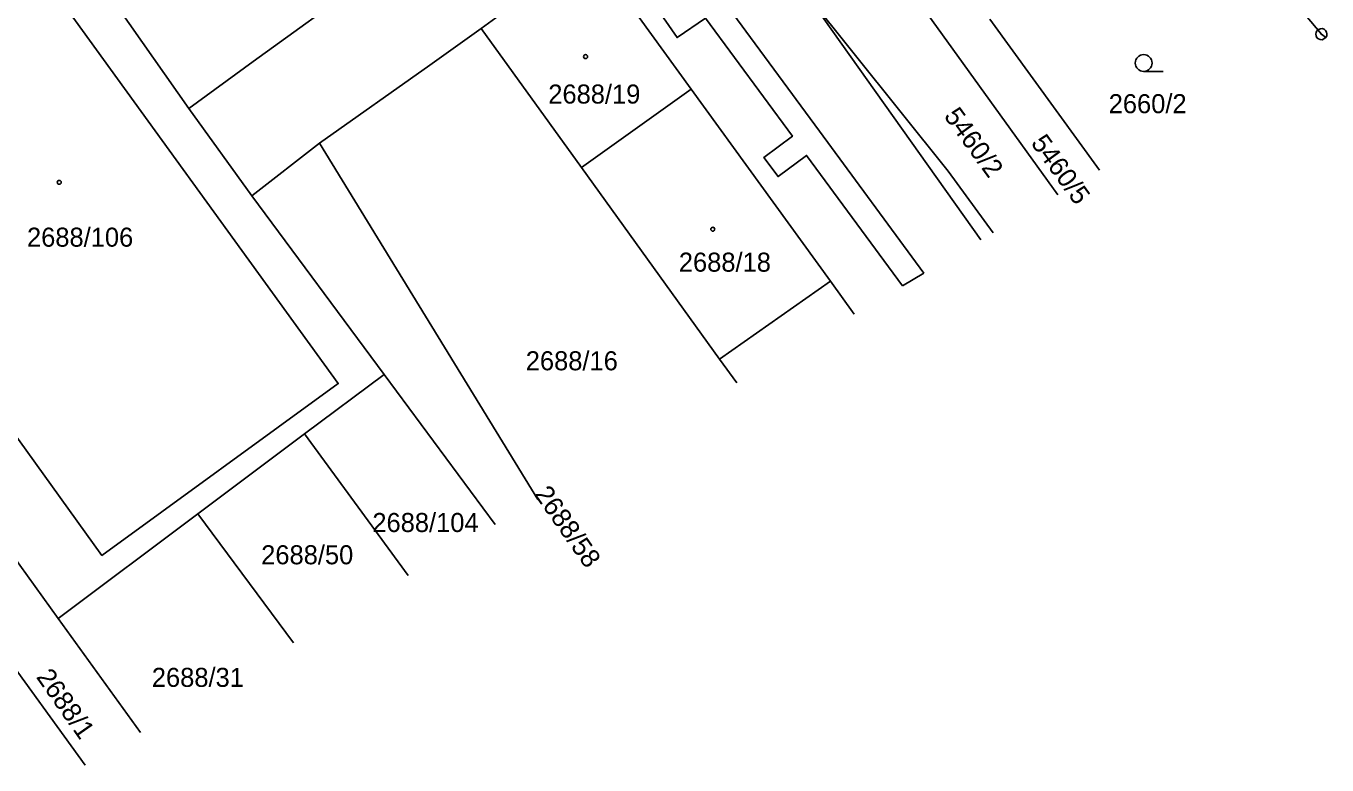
# Model space of a CAD drawing. Extents: x -821458 to -820266, y -1071458 to -1069826.
# Drawn here: x -820637.8 to -820521.7, y -1071458.4 to -1071392.4 of the extents above; entities that cross this region are included whole.
import ezdxf

# ---------------------------------------------------------------- set-up
doc = ezdxf.new("R2010")
doc.units = 0
for name, color, linetype in [('Vrstva 1', 7, 'Continuous'), ('Vrstva 13', 7, 'Continuous'), ('Vrstva 2', 7, 'Continuous'), ('Vrstva 3', 7, 'Continuous'), ('Vrstva 4', 7, 'Continuous'), ('Vrstva 5', 7, 'Continuous'), ('Vrstva 8', 7, 'Continuous')]:
    doc.layers.add(name, color=color, linetype=linetype)

msp = doc.modelspace()

# ---------------------------------------------------------------- linework, layer by layer
at = {"layer": 'Vrstva 1'}
for p, q in [((-820578.44, -1071398.07), (-820587.38, -1071385.73)), ((-820629.59, -1071390.8), (-820623.29, -1071399.8)), ((-820551.8, -1071391.81), (-820542, -1071405.29)), ((-820588.24, -1071405.05), (-820597.2, -1071392.64)), ((-820578.44, -1071398.07), (-820588.24, -1071405.05)), ((-820566.03, -1071415.2), (-820578.44, -1071398.07)), ((-820623.29, -1071399.8), (-820617.66, -1071407.57)), ((-820575.91, -1071422.15), (-820588.24, -1071405.05)), ((-820617.66, -1071407.57), (-820605.86, -1071423.52)), ((-820566.03, -1071415.2), (-820575.91, -1071422.15)), ((-820563.91, -1071418.13), (-820566.03, -1071415.2)), ((-820652.54, -1071420.92), (-820634.93, -1071445.29)), ((-820574.38, -1071424.27), (-820575.91, -1071422.15)), ((-820605.86, -1071423.52), (-820612.95, -1071428.83)), ((-820605.86, -1071423.52), (-820595.95, -1071436.92)), ((-820612.95, -1071428.83), (-820622.48, -1071435.96)), ((-820603.7, -1071441.46), (-820612.95, -1071428.83)), ((-820622.48, -1071435.96), (-820634.93, -1071445.29)), ((-820613.93, -1071447.46), (-820622.48, -1071435.96)), ((-820644.49, -1071441.9), (-820632.54, -1071458.37)), ((-820634.93, -1071445.29), (-820627.58, -1071455.46))]:
    msp.add_line(p, q, dxfattribs=at)
for points in [[(-820521.8, -1071393.45), (-820522.21, -1071393.16), (-820534.12, -1071378.97)], [(-820545.73, -1071407.48), (-820562.09, -1071384.76)], [(-820597.2, -1071392.64), (-820595.89, -1071391.71), (-820587.38, -1071385.73)], [(-820605.49, -1071386.9), (-820607.39, -1071388.24), (-820617.53, -1071395.61), (-820623.29, -1071399.8)], [(-820636.76, -1071387.29), (-820609.95, -1071424.33), (-820631.03, -1071439.67), (-820644.44, -1071421.08), (-820639.9, -1071417.79), (-820653.43, -1071399.1)], [(-820568.23, -1071389.49), (-820555.51, -1071405.39), (-820551.51, -1071410.87)], [(-820568.23, -1071389.49), (-820552.6, -1071411.51)], [(-820617.66, -1071407.57), (-820611.61, -1071402.88), (-820601.76, -1071395.91), (-820597.2, -1071392.64)]]:
    msp.add_lwpolyline(points, dxfattribs=at)
at = {"layer": 'Vrstva 13'}
msp.add_line((-820559.59, -1071415.6), (-820557.68, -1071414.49), dxfattribs=at)
for points in [[(-820557.68, -1071414.49), (-820567.01, -1071401.8), (-820575.97, -1071389.59)], [(-820580.91, -1071391.7), (-820579.71, -1071393.46), (-820577.16, -1071391.72), (-820569.42, -1071402.27), (-820571.96, -1071404.16), (-820570.7, -1071405.86), (-820568.15, -1071403.97), (-820559.59, -1071415.6)]]:
    msp.add_lwpolyline(points, dxfattribs=at)
at = {"layer": 'Vrstva 3'}
msp.add_line((-820538.07, -1071396.48), (-820536.32, -1071396.48), dxfattribs=at)
msp.add_circle((-820538.07, -1071395.73), 0.75, dxfattribs=at)
at = {"layer": 'Vrstva 4'}
msp.add_line((-820611.61, -1071402.88), (-820592.13, -1071434.68), dxfattribs=at)
at = {"layer": 'Vrstva 5'}
for centre in [(-820587.87, -1071395.16), (-820634.84, -1071406.38), (-820576.52, -1071410.56)]:
    msp.add_circle(centre, 0.175, dxfattribs=at)
at = {"layer": 'Vrstva 8'}
msp.add_line((-820522.15, -1071393.66), (-820521.81, -1071393.45), dxfattribs=at)
msp.add_circle((-820522.21, -1071393.16), 0.0303, dxfattribs=at)
msp.add_arc((-820522.21, -1071393.16), 0.5, 323.9672, 276.7903, dxfattribs=at)

# ---------------------------------------------------------------- texts
at = {"layer": 'Vrstva 2'}
for s, p in [('2688/19', (-820591.2, -1071399.35)), ('2660/2', (-820541.19, -1071400.21)), ('2688/106', (-820637.72, -1071412.12)), ('2688/18', (-820579.55, -1071414.35)), ('2688/16', (-820593.21, -1071423.15)), ('2688/104', (-820606.9, -1071437.58)), ('2688/50', (-820616.82, -1071440.46)), ('2688/31', (-820626.58, -1071451.4))]:
    msp.add_text(s, height=1.7, dxfattribs=at).set_placement(p)
for s, rotation, p in [('5460/2', 306, (-820555.95, -1071400.48)), ('5460/5', 306, (-820548.19, -1071402.89)), ('2688/58', 305, (-820592.51, -1071434.2)), ('2688/1', 305, (-820636.95, -1071450.52))]:
    msp.add_text(s, height=1.7, rotation=rotation, dxfattribs=at).set_placement(p)

doc.saveas('drawing.dxf')
